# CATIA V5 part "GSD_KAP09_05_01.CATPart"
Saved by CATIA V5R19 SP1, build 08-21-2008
Part number: GSD_REPETITION_04
Description: Beispielmodell: Kreismuster  Maik Hertha IT Consultants
Bounding box of the stored display mesh (mm): x -71.181 to 128.819, y -65.486 to 134.51, z 20 to 55
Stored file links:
  \GSD_LOFT\GSD_REPETITION_04.CATPart
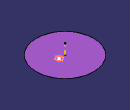
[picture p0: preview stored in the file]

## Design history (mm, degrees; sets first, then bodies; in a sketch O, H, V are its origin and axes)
AxisSystem1: origin (0, 0, 0), X (1, 0, 0), Y (0, 1, 0), Z (0, 0, 1)
Set1
  Plane1: type Equation, A 0, B 0, C 1, RefAxis AxisSystem1, Length 20
  Sketch1 on Plane1, origin (0, 0, 20), H (1, 0, 0), V (0, 1, 0)
    circle A1 centre (28.8189, 34.5124) radius 100
    radius A1 = 100
  Split1: ToCut Plane1, Cutting Sketch1
  Point1: type OnSurface, Support Split1, Direction (0.2848, -0.9586, 0), Length 0
  Line1: type Normal, RefSkin Split1, Start 0, End 35, RefPoint Point1
  Sketch2 on Plane1, origin (48.8189, 34.5124, 20), H (1, 0, 0), V (0, 1, 0)
    point P1 (-0.0677, -10.9694)
    point P2 (9.466, -5.5433)
    point P3 (9.5336, 5.4261)
    point P4 (0.0677, 10.9694)
    point P5 (-9.466, 5.5433)
    point P6 (-9.5336, -5.4261)
    point P7 (4.6992, -8.2564)
    line L1 (-0.0677, -10.9694) -> (9.466, -5.5433)
    line L2 (9.466, -5.5433) -> (9.5336, 5.4261)
    line L3 (9.5336, 5.4261) -> (0.0677, 10.9694)
    line L4 (0.0677, 10.9694) -> (-9.466, 5.5433)
    line L5 (-9.466, 5.5433) -> (-9.5336, -5.4261)
    line L6 (-9.5336, -5.4261) -> (-0.0677, -10.9694)
    construction line L7 (0, 0) -> (4.6992, -8.2564)
    construction circle A1 centre (0, 0) radius 10.9697
    construction arc A2 centre (-9.466, 5.5433) radius 10.9697 from (0.0677, 10.9694) to (-9.5336, -5.4261) cw
    construction arc A3 centre (9.466, -5.5433) radius 10.9697 from (9.5336, 5.4261) to (-0.0677, -10.9694) ccw
    curve C1
    distance L1 L4 = 19
    coincidence: A1 P1, A1 P2, A1 P3, A1 P4, A1 P5, A1 P6, A2 O, A3 O
    midpoint: P7 L1
  Point2: type OnSurface, Support Split1, Direction (1, 0, 0), Length 20, RefPoint Point1
Body1 (main body)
